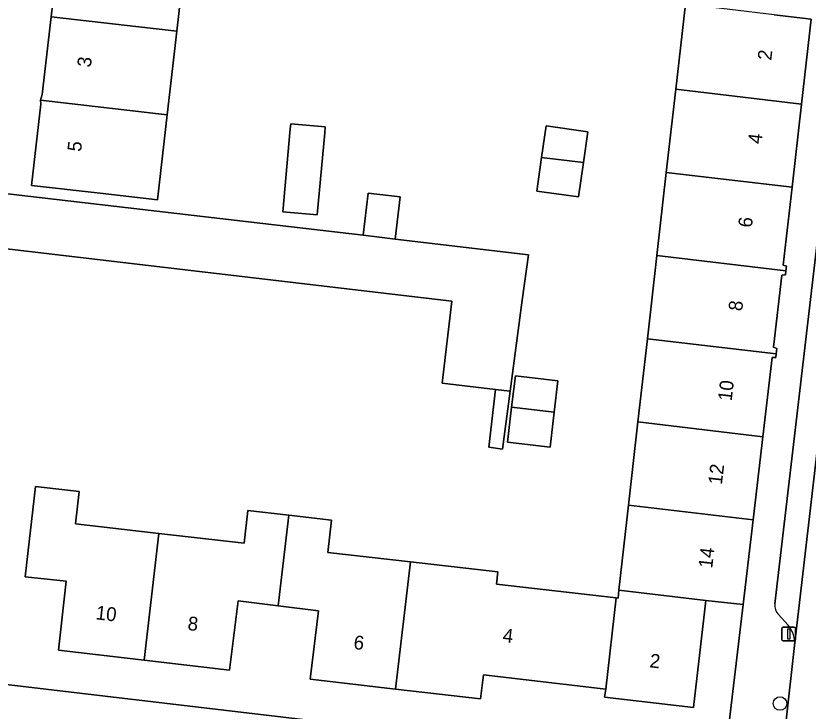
# Model space of a CAD drawing. Extents: x 161241 to 161758, y 384138 to 384885.
# Drawn here: x 161399.9 to 161457.1, y 384579.4 to 384629.6 of the extents above; entities that cross this region are included whole.
import ezdxf

# ---------------------------------------------------------------- set-up
doc = ezdxf.new("R2010")
doc.units = 0
for name, color, linetype in [('IMGEO_Boom', 7, 'Continuous'), ('IMGEO_Erf', 7, 'Continuous'), ('IMGEO_Lichtmast', 7, 'Continuous'), ('IMGEO_Pand', 7, 'Continuous'), ('IMGEO_Pand_nummerreeks', 7, 'Continuous'), ('IMGEO_Parkeervlak_open', 7, 'Continuous'), ('IMGEO_Rijbaan_lokaal_open', 7, 'Continuous'), ('IMGEO_Voetpad_open', 7, 'Continuous')]:
    doc.layers.add(name, color=color, linetype=linetype)

msp = doc.modelspace()

# ---------------------------------------------------------------- linework, layer by layer
at = {"layer": 'IMGEO_Boom'}
msp.add_circle((161455.104, 384579.929), 0.489, dxfattribs=at)
at = {"layer": 'IMGEO_Erf'}
for points in [[(161458.589, 384639.718), (161400.088, 384646.416), (161397.281, 384622.401), (161396.961, 384619.66), (161396.655, 384617.039), (161425.024, 384613.724), (161425.387, 384616.773), (161427.698, 384616.498), (161427.335, 384613.449), (161436.939, 384612.308), (161436.503, 384609.048), (161435.624, 384602.469), (161435.067, 384598.3), (161434.079, 384598.432), (161434.571, 384602.594), (161430.726, 384603.048), (161431.421, 384608.981), (161396.194, 384613.099), (161395.453, 384606.759), (161397.13, 384605.671), (161394.834, 384585.76), (161392.961, 384585.251), (161392.905, 384584.764)], [(161412.261, 384634.649), (161411.558, 384628.452), (161410.875, 384622.429), (161410.179, 384616.297), (161406.04, 384616.766), (161401.071, 384617.33), (161401.757, 384623.196), (161401.735, 384623.479), (161401.847, 384623.9), (161402.492, 384629.494), (161403.198, 384635.612)], [(161444.173, 384594.246), (161444.854, 384600.251), (161445.535, 384606.257), (161446.216, 384612.263), (161446.897, 384618.268), (161447.578, 384624.274), (161448.273, 384630.403)], [(161454.687, 384629.637), (161457.357, 384629.317)], [(161451.231, 384576.957), (161452.444, 384587.078), (161449.745, 384587.378), (161448.852, 384579.646), (161442.442, 384580.381), (161442.522, 384580.974), (161433.704, 384581.995), (161433.494, 384580.26), (161427.352, 384580.978), (161421.194, 384581.698), (161421.794, 384586.626), (161418.877, 384586.981), (161415.986, 384587.333), (161415.378, 384582.349), (161409.204, 384583.067), (161403.027, 384583.786), (161403.59, 384588.758), (161400.621, 384589.08), (161401.374, 384595.587), (161404.515, 384595.231), (161404.25, 384592.895), (161410.271, 384592.212), (161416.421, 384591.514), (161416.686, 384593.858), (161419.64, 384593.523), (161422.727, 384593.172), (161422.462, 384590.836), (161428.424, 384590.16), (161434.733, 384589.444), (161434.63, 384588.539), (161443.269, 384587.558), (161443.413, 384587.542), (161443.478, 384588.118), (161444.173, 384594.246)], [(161393.526, 384581.977), (161448.824, 384575.465)]]:
    msp.add_lwpolyline(points, dxfattribs=at)
for points in [[(161419.21, 384615.429), (161419.753, 384621.409), (161419.786, 384621.771), (161422.285, 384621.544), (161422.247, 384621.123), (161421.709, 384615.202)], [(161437.896, 384619.331), (161438.221, 384621.627), (161441.223, 384621.202), (161440.909, 384618.975), (161440.558, 384616.494), (161437.555, 384616.92)], [(161435.434, 384598.786), (161435.734, 384601.328), (161436.002, 384603.592), (161439.072, 384603.23), (161438.805, 384600.965), (161438.505, 384598.423)]]:
    msp.add_lwpolyline(points, close=True, dxfattribs=at)
at = {"layer": 'IMGEO_Lichtmast'}
for p, q in [((161455.238, 384584.554), (161455.238, 384585.354)), ((161455.238, 384585.354), (161455.238, 384584.554)), ((161455.338, 384585.454), (161456.128, 384585.454)), ((161456.128, 384585.454), (161455.338, 384585.454)), ((161456.228, 384585.354), (161456.228, 384584.554)), ((161456.228, 384584.554), (161456.228, 384585.354)), ((161456.128, 384584.454), (161455.338, 384584.454)), ((161455.338, 384584.454), (161456.128, 384584.454))]:
    msp.add_line(p, q, dxfattribs=at)
msp.add_lwpolyline([(161455.658, 384585.329), (161455.808, 384585.329), (161455.808, 384584.579), (161455.658, 384584.579), (161455.658, 384585.329)], dxfattribs=at)
for centre, start, end in [((161455.338, 384585.354), 90, 180), ((161455.338, 384585.354), 90, 180), ((161456.128, 384585.354), 0, 90), ((161456.128, 384585.354), 360, 90), ((161455.338, 384584.554), 180, 270), ((161455.338, 384584.554), 180, 270), ((161456.128, 384584.554), 270, 0), ((161456.128, 384584.554), 270, 0)]:
    msp.add_arc(centre, 0.1, start, end, dxfattribs=at)
at = {"layer": 'IMGEO_Pand'}
for points in [[(161405.886, 384635.325), (161403.198, 384635.612), (161402.492, 384629.494), (161411.558, 384628.452), (161412.261, 384634.649)], [(161457.357, 384629.317), (161454.687, 384629.637), (161448.273, 384630.403), (161447.578, 384624.274), (161456.659, 384623.201)], [(161402.492, 384629.494), (161401.847, 384623.9), (161401.735, 384623.479), (161410.875, 384622.429), (161411.558, 384628.452)], [(161456.659, 384623.201), (161447.578, 384624.274), (161446.897, 384618.268), (161455.974, 384617.196)], [(161401.735, 384623.479), (161401.757, 384623.196), (161401.071, 384617.33), (161406.04, 384616.766), (161410.179, 384616.297), (161410.875, 384622.429)], [(161422.247, 384621.123), (161422.285, 384621.544), (161419.786, 384621.771), (161419.753, 384621.409), (161419.21, 384615.429), (161421.709, 384615.202)], [(161437.896, 384619.331), (161440.909, 384618.975), (161441.223, 384621.202), (161438.221, 384621.627)], [(161440.909, 384618.975), (161437.896, 384619.331), (161437.555, 384616.92), (161440.558, 384616.494)], [(161455.572, 384611.504), (161455.331, 384611.563), (161455.974, 384617.196), (161446.897, 384618.268), (161446.216, 384612.263), (161455.534, 384611.162)], [(161425.024, 384613.724), (161426.205, 384613.584), (161427.335, 384613.449), (161427.698, 384616.498), (161425.387, 384616.773)], [(161454.886, 384605.544), (161454.623, 384605.64), (161455.243, 384610.845), (161455.503, 384610.877), (161455.534, 384611.162), (161446.216, 384612.263), (161445.535, 384606.257), (161454.831, 384605.159)], [(161454.55, 384604.913), (161454.795, 384604.905), (161454.831, 384605.159), (161445.535, 384606.257), (161444.854, 384600.251), (161453.874, 384599.186)], [(161435.734, 384601.328), (161438.805, 384600.965), (161439.072, 384603.23), (161436.002, 384603.592)], [(161438.805, 384600.965), (161435.734, 384601.328), (161435.434, 384598.786), (161438.505, 384598.423)], [(161453.874, 384599.186), (161444.854, 384600.251), (161444.173, 384594.246), (161453.165, 384593.184)], [(161410.271, 384592.212), (161404.25, 384592.895), (161404.515, 384595.231), (161401.374, 384595.587), (161400.621, 384589.08), (161403.59, 384588.758), (161403.027, 384583.786), (161409.204, 384583.067)], [(161453.165, 384593.184), (161444.173, 384594.246), (161443.478, 384588.118), (161449.745, 384587.378), (161452.444, 384587.078)], [(161419.64, 384593.523), (161416.686, 384593.858), (161416.421, 384591.514), (161410.271, 384592.212), (161409.204, 384583.067), (161415.378, 384582.349), (161415.986, 384587.333), (161418.877, 384586.981)], [(161418.877, 384586.981), (161421.794, 384586.626), (161421.194, 384581.698), (161427.352, 384580.978), (161428.424, 384590.16), (161422.462, 384590.836), (161422.727, 384593.172), (161419.64, 384593.523)], [(161443.269, 384587.558), (161434.63, 384588.539), (161434.733, 384589.444), (161428.424, 384590.16), (161427.352, 384580.978), (161433.494, 384580.26), (161433.704, 384581.995), (161442.522, 384580.974)], [(161442.522, 384580.974), (161442.442, 384580.381), (161448.852, 384579.646), (161449.745, 384587.378), (161443.478, 384588.118), (161443.413, 384587.542), (161443.269, 384587.558)]]:
    msp.add_lwpolyline(points, close=True, dxfattribs=at)
at = {"layer": 'IMGEO_Parkeervlak_open'}
for points in [[(161456.155, 384584.108), (161458.88, 384607.496), (161459.201, 384610.247), (161461.735, 384631.999)], [(161459.649, 384629.015), (161454.735, 384587.127)], [(161454.976, 384586.37), (161455.684, 384585.583)]]:
    msp.add_lwpolyline(points, dxfattribs=at)
for centre, radius, start, end in [((161455.695, 384587.016), 0.967, 173.3936, 221.9254), ((161454.163, 384584.285), 2, 354.9367, 40.4821)]:
    msp.add_arc(centre, radius, start, end, dxfattribs=at)
at = {"layer": 'IMGEO_Rijbaan_lokaal_open'}
for points in [[(161436.939, 384612.308), (161427.335, 384613.449), (161426.205, 384613.584), (161425.024, 384613.724), (161396.655, 384617.039), (161396.194, 384613.099), (161431.421, 384608.981), (161430.726, 384603.048), (161434.571, 384602.594), (161435.624, 384602.469), (161436.503, 384609.048)], [(161458.88, 384607.496), (161456.155, 384584.108), (161455.501, 384578.293), (161455.326, 384576.798), (161454.02, 384565.608), (161453.187, 384558.455), (161452.178, 384549.677), (161458.115, 384548.986), (161459.149, 384557.883), (161459.972, 384564.87), (161461.287, 384576.027), (161461.494, 384577.785), (161462.171, 384583.365), (161464.9, 384606.794)]]:
    msp.add_lwpolyline(points, close=True, dxfattribs=at)
at = {"layer": 'IMGEO_Voetpad_open'}
for points in [[(161457.357, 384629.317), (161456.659, 384623.201), (161455.974, 384617.196), (161455.331, 384611.563), (161455.572, 384611.504), (161455.534, 384611.162), (161455.503, 384610.877), (161455.243, 384610.845), (161454.623, 384605.64), (161454.886, 384605.544), (161454.831, 384605.159), (161454.795, 384604.905), (161454.55, 384604.913), (161453.874, 384599.186), (161453.165, 384593.184), (161452.444, 384587.078), (161451.231, 384576.957)], [(161454.735, 384587.127), (161459.649, 384629.015)], [(161455.684, 384585.583), (161454.976, 384586.37)], [(161453.187, 384558.455), (161454.02, 384565.608), (161453.524, 384565.665), (161454.83, 384576.855), (161455.326, 384576.798), (161455.501, 384578.293), (161456.155, 384584.108)], [(161448.824, 384575.465), (161393.526, 384581.977)]]:
    msp.add_lwpolyline(points, dxfattribs=at)
msp.add_lwpolyline([(161435.624, 384602.469), (161434.571, 384602.594), (161434.079, 384598.432), (161435.067, 384598.3)], close=True, dxfattribs=at)
for centre, radius, start, end in [((161455.695, 384587.016), 0.967, 173.3936, 221.9254), ((161454.163, 384584.285), 2, 354.9367, 40.4821)]:
    msp.add_arc(centre, radius, start, end, dxfattribs=at)

# ---------------------------------------------------------------- texts
at = {"layer": 'IMGEO_Pand_nummerreeks'}
for s, rotation, p in [('3', 83.3638, (161405.361, 384625.818)), ('2', 83.3655, (161454.471, 384626.315)), ('4', 83.3655, (161453.77, 384620.283)), ('5', 83.3638, (161404.652, 384619.724)), ('6', 83.3655, (161453.068, 384614.249)), ('8', 83.3655, (161452.366, 384608.219)), ('10', 83.3655, (161451.611, 384601.727)), ('12', 83.3655, (161450.908, 384595.687)), ('14', 83.3655, (161450.207, 384589.656)), ('10', 353.3637, (161405.679, 384586.014)), ('8', 353.3637, (161412.311, 384585.243)), ('6', 353.3318, (161424.288, 384583.873)), ('4', 353.3954, (161435.053, 384584.375)), ('2', 353.4588, (161445.658, 384582.549))]:
    msp.add_text(s, height=1, rotation=rotation, dxfattribs=at).set_placement(p)

doc.saveas('drawing.dxf')
